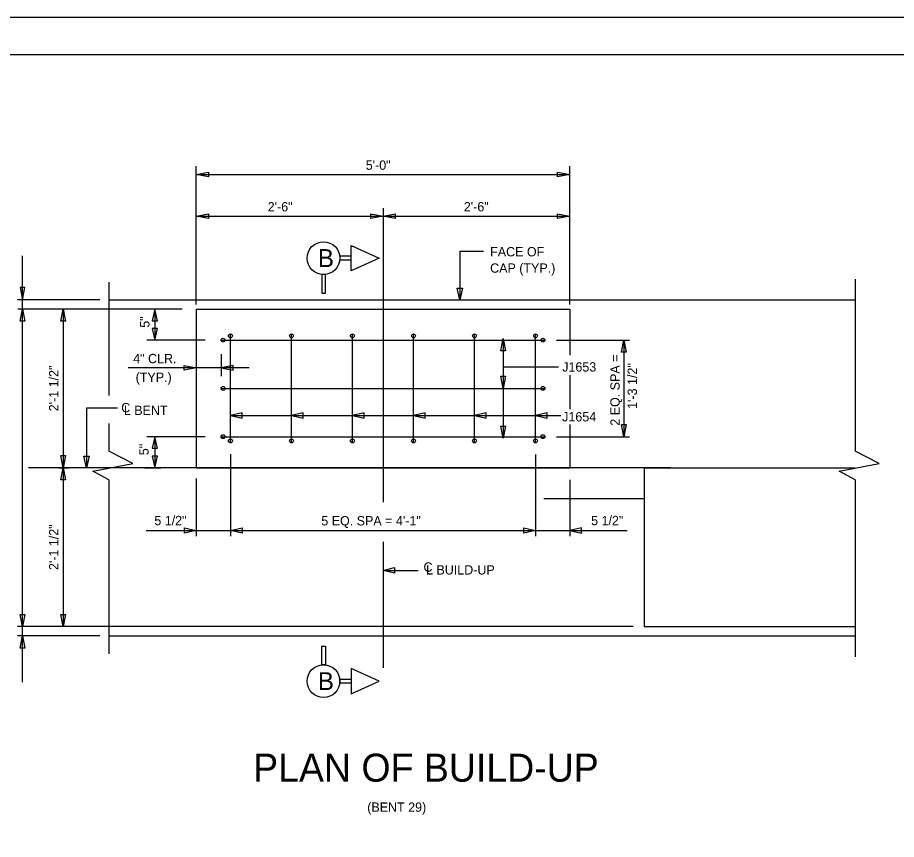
# Model space of a CAD drawing. Extents: x -133.1 to -97, y -58.4 to -36.4.
# Drawn here: x -119.58 to -107.81, y -47.4 to -36.4 of the extents above; entities that cross this region are included whole.
import ezdxf

# ---------------------------------------------------------------- set-up
doc = ezdxf.new("R2010")
doc.units = 0
for name, color, linetype in [('BR_AUTO DIMENSION', 7, 'Continuous'), ('BR_BORDER LINES', 7, 'Continuous'), ('BR_CENTER LINES', 7, 'Continuous'), ('BR_CONCRETE', 7, 'Continuous'), ('BR_REBAR', 7, 'Continuous'), ('BR_TEXT', 7, 'Continuous'), ('Default', 7, 'Continuous'), ('Level 31', 7, 'Continuous')]:
    doc.layers.add(name, color=color, linetype=linetype)

msp = doc.modelspace()

# ---------------------------------------------------------------- linework, layer by layer
at = {"layer": 'BR_AUTO DIMENSION'}
for p, q in [((-117.186, -40.237), (-117.186, -38.388)), ((-112.186, -40.237), (-112.186, -38.388)), ((-117.186, -38.498), (-112.186, -38.498)), ((-114.686, -38.949), (-114.686, -39.18)), ((-117.186, -39.055), (-114.686, -39.055)), ((-114.686, -39.055), (-112.186, -39.055)), ((-113.656, -39.525), (-113.656, -40.175)), ((-113.656, -39.525), (-113.339, -39.525)), ((-119.511, -40.3), (-119.511, -39.586)), ((-118.476, -40.175), (-119.577, -40.175)), ((-117.374, -40.3), (-119.573, -40.3)), ((-119.511, -45.296), (-119.511, -40.3)), ((-118.969, -40.3), (-118.969, -42.425)), ((-117.739, -40.3), (-117.739, -40.716)), ((-113.076, -40.696), (-113.076, -42.029)), ((-117.066, -40.716), (-117.846, -40.716)), ((-112.363, -40.716), (-111.385, -40.716)), ((-111.462, -40.716), (-111.462, -42.008)), ((-116.853, -40.904), (-116.853, -41.197)), ((-116.476, -41.085), (-118.096, -41.085)), ((-113.076, -41.072), (-112.335, -41.072)), ((-118.242, -41.625), (-118.654, -41.625)), ((-118.654, -41.625), (-118.654, -42.425)), ((-116.728, -41.726), (-112.305, -41.726)), ((-117.066, -42.008), (-117.846, -42.008)), ((-117.739, -42.029), (-117.739, -42.425)), ((-112.363, -42.008), (-111.385, -42.008)), ((-116.728, -42.24), (-116.728, -43.34)), ((-112.645, -42.246), (-112.645, -43.34)), ((-119.025, -42.425), (-118.889, -42.425)), ((-118.969, -42.425), (-118.969, -44.55)), ((-117.873, -42.425), (-117.658, -42.425)), ((-117.186, -42.569), (-117.186, -43.34)), ((-112.186, -42.584), (-112.186, -43.34)), ((-117.858, -43.263), (-111.417, -43.263)), ((-114.686, -43.797), (-114.215, -43.797)), ((-111.338, -44.55), (-119.577, -44.55)), ((-118.476, -44.675), (-119.577, -44.675))]:
    msp.add_line(p, q, dxfattribs=at)
for points in [[(-117.024, -38.53), (-117.186, -38.498), (-117.024, -38.467)], [(-112.349, -38.467), (-112.186, -38.498), (-112.349, -38.53)], [(-117.024, -39.087), (-117.186, -39.055), (-117.024, -39.024)], [(-114.849, -39.024), (-114.686, -39.055), (-114.849, -39.087)], [(-114.524, -39.087), (-114.686, -39.055), (-114.524, -39.024)], [(-112.349, -39.024), (-112.186, -39.055), (-112.349, -39.087)], [(-119.542, -40.012), (-119.511, -40.175), (-119.479, -40.012)], [(-113.62, -40.019), (-113.656, -40.175), (-113.692, -40.019)], [(-119.542, -40.462), (-119.511, -40.3), (-119.479, -40.462)], [(-119, -40.462), (-118.969, -40.3), (-118.937, -40.462)], [(-117.703, -40.456), (-117.739, -40.3), (-117.775, -40.456)], [(-117.775, -40.56), (-117.739, -40.716), (-117.703, -40.56)], [(-113.107, -40.858), (-113.076, -40.696), (-113.045, -40.858)], [(-111.493, -40.879), (-111.462, -40.716), (-111.43, -40.879)], [(-117.349, -41.054), (-117.186, -41.085), (-117.349, -41.116)], [(-116.69, -41.054), (-116.853, -41.085), (-116.69, -41.116)], [(-113.045, -41.2), (-113.076, -41.362), (-113.107, -41.2)], [(-116.572, -41.69), (-116.728, -41.726), (-116.572, -41.762)], [(-115.755, -41.69), (-115.911, -41.726), (-115.755, -41.762)], [(-114.939, -41.69), (-115.095, -41.726), (-114.939, -41.762)], [(-114.122, -41.69), (-114.278, -41.726), (-114.122, -41.762)], [(-113.305, -41.69), (-113.461, -41.726), (-113.305, -41.762)], [(-112.489, -41.69), (-112.645, -41.726), (-112.489, -41.762)], [(-113.045, -41.866), (-113.076, -42.029), (-113.107, -41.866)], [(-111.43, -41.846), (-111.462, -42.008), (-111.493, -41.846)], [(-117.703, -42.164), (-117.739, -42.008), (-117.775, -42.164)], [(-118.937, -42.262), (-118.969, -42.425), (-119, -42.262)], [(-118.618, -42.269), (-118.654, -42.425), (-118.69, -42.269)], [(-117.775, -42.269), (-117.739, -42.425), (-117.703, -42.269)], [(-119, -42.587), (-118.969, -42.425), (-118.937, -42.587)], [(-117.342, -43.227), (-117.186, -43.263), (-117.342, -43.299)], [(-116.572, -43.299), (-116.728, -43.263), (-116.572, -43.227)], [(-112.801, -43.227), (-112.645, -43.263), (-112.801, -43.299)], [(-112.03, -43.227), (-112.186, -43.263), (-112.03, -43.299)], [(-114.53, -43.833), (-114.686, -43.797), (-114.53, -43.761)], [(-119.479, -44.387), (-119.511, -44.55), (-119.542, -44.387)], [(-118.937, -44.387), (-118.969, -44.55), (-119, -44.387)], [(-119.542, -44.837), (-119.511, -44.675), (-119.479, -44.837)]]:
    msp.add_lwpolyline(points, close=True, dxfattribs=at)
at = {"layer": 'BR_BORDER LINES'}
msp.add_line((-97.642, -36.899), (-131.308, -36.899), dxfattribs=at)
at = {"layer": 'BR_CENTER LINES'}
for p, q in [((-114.686, -39.168), (-114.686, -42.884)), ((-110.839, -42.425), (-119.429, -42.425)), ((-114.686, -43.417), (-114.686, -45.103))]:
    msp.add_line(p, q, dxfattribs=at)
at = {"layer": 'BR_CONCRETE'}
for p, q in [((-118.356, -40.175), (-108.364, -40.175)), ((-117.186, -40.3), (-117.186, -42.425)), ((-117.186, -40.3), (-112.186, -40.3)), ((-112.186, -40.3), (-112.186, -40.917)), ((-112.186, -41.187), (-112.186, -41.639)), ((-112.186, -41.846), (-112.186, -42.425)), ((-117.186, -42.425), (-112.186, -42.425)), ((-111.189, -42.425), (-111.189, -44.55)), ((-111.189, -42.425), (-108.364, -42.425)), ((-111.189, -44.55), (-108.364, -44.55)), ((-118.356, -44.675), (-108.364, -44.675))]:
    msp.add_line(p, q, dxfattribs=at)
at = {"layer": 'BR_REBAR'}
for p, q in [((-116.728, -42.091), (-116.728, -40.633)), ((-115.911, -42.091), (-115.911, -40.633)), ((-115.095, -42.091), (-115.095, -40.633)), ((-114.278, -42.091), (-114.278, -40.633)), ((-113.461, -42.091), (-113.461, -40.633)), ((-112.645, -42.091), (-112.645, -40.633)), ((-116.853, -40.716), (-112.52, -40.716)), ((-116.853, -41.362), (-112.52, -41.362)), ((-116.853, -42.008), (-112.52, -42.008))]:
    msp.add_line(p, q, dxfattribs=at)
for centre, radius in [((-116.827, -40.716), 0.026), ((-116.728, -40.659), 0.0261), ((-115.911, -40.659), 0.0261), ((-115.095, -40.659), 0.0261), ((-114.278, -40.659), 0.0261), ((-113.461, -40.659), 0.0261), ((-112.645, -40.659), 0.0261), ((-112.546, -40.716), 0.026), ((-116.827, -41.362), 0.026), ((-112.546, -41.362), 0.026), ((-116.827, -42.008), 0.026), ((-112.546, -42.008), 0.026), ((-116.728, -42.065), 0.0261), ((-115.911, -42.065), 0.0261), ((-115.095, -42.065), 0.0261), ((-114.278, -42.065), 0.0261), ((-113.461, -42.065), 0.0261), ((-112.645, -42.065), 0.0261)]:
    msp.add_circle(centre, radius, dxfattribs=at)
at = {"layer": 'BR_TEXT'}
for points in [[(-115.113, -39.45), (-114.737, -39.618), (-115.113, -39.787)], [(-115.263, -39.643), (-115.113, -39.643), (-115.113, -39.593), (-115.263, -39.593)], [(-115.507, -40.088), (-115.457, -40.088), (-115.457, -39.837), (-115.507, -39.837)], [(-115.507, -44.811), (-115.457, -44.811), (-115.457, -45.061), (-115.507, -45.061)], [(-115.113, -45.449), (-114.737, -45.28), (-115.113, -45.111)], [(-115.263, -45.255), (-115.113, -45.255), (-115.113, -45.305), (-115.263, -45.305)]]:
    msp.add_lwpolyline(points, close=True, dxfattribs=at)
for centre in [(-115.482, -39.618), (-115.482, -45.28)]:
    msp.add_circle(centre, 0.219, dxfattribs=at)
at = {"layer": 'Default'}
for p, q in [((-118.356, -39.94), (-118.356, -41.459)), ((-108.364, -39.9), (-108.364, -42.204)), ((-118.356, -41.831), (-118.356, -42.204)), ((-118.356, -42.587), (-118.356, -44.914)), ((-108.364, -42.587), (-108.364, -44.953))]:
    msp.add_line(p, q, dxfattribs=at)
for points in [[(-118.356, -42.587), (-118.572, -42.469), (-118.036, -42.368), (-118.356, -42.204)], [(-108.364, -42.587), (-108.58, -42.469), (-108.044, -42.368), (-108.364, -42.204)]]:
    msp.add_lwpolyline(points, dxfattribs=at)
at = {"layer": 'Level 31'}
msp.add_line((-111.189, -42.841), (-112.532, -42.841), dxfattribs=at)
msp.add_lwpolyline([(-133.141, -58.399), (-97.141, -58.399), (-97.141, -36.399), (-133.141, -36.399)], close=True, dxfattribs=at)

# ---------------------------------------------------------------- texts
at = {"layer": 'BR_AUTO DIMENSION'}
for s, p in [('5\'-0"', (-114.917, -38.436)), ('2\'-6"', (-116.229, -38.993)), ('2\'-6"', (-113.604, -38.993)), ('FACE OF', (-113.252, -39.595)), ('CAP (TYP.)', (-113.252, -39.814)), ('4" CLR.', (-118.03, -41.025)), ('J1653', (-112.287, -41.137)), ('(TYP.)', (-117.997, -41.275)), ('J1654', (-112.288, -41.804)), ('5 EQ. SPA = 4\'-1"', (-115.512, -43.196)), ('C', (-114.144, -43.816)), ('L BUILD-UP', (-114.11, -43.853)), ('(BENT 29)', (-114.897, -47.029))]:
    msp.add_text(s, height=0.125, dxfattribs=at).set_placement(p)
for s, rotation, p in [('2 EQ. SPA =', 90, (-111.518, -41.861)), ('1\'-3 1/2"', 90, (-111.287, -41.636)), ('2\'-1 1/2"', 90, (-119.031, -41.668)), ('5 1/2"', 360, (-117.747, -43.193)), ('5 1/2"', 360, (-111.9, -43.193)), ('2\'-1 1/2"', 90, (-119.031, -43.793))]:
    msp.add_text(s, height=0.125, rotation=rotation, dxfattribs=at).set_placement(p)
at = {"layer": 'BR_TEXT'}
for s, height, p in [('B', 0.24, (-115.557, -39.738)), ('B', 0.24, (-115.557, -45.4)), ('PLAN OF BUILD-UP', 0.375, (-116.424, -46.626))]:
    msp.add_text(s, height=height, dxfattribs=at).set_placement(p)
for s, rotation, p in [('5"', 90, (-117.812, -40.55)), ('C', 360, (-118.19, -41.682)), ('L BENT', 360, (-118.155, -41.718)), ('5"', 90, (-117.823, -42.256))]:
    msp.add_text(s, height=0.125, rotation=rotation, dxfattribs=at).set_placement(p)

doc.saveas('drawing.dxf')
